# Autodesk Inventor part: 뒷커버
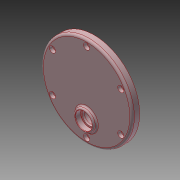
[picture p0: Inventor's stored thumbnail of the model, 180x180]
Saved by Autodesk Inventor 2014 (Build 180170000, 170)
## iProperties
Created: 2024-02
Part Number: 뒷커버
Material: 알루미늄 6061
Document SubType Name: Modeling
Designer: mdu-01
Density: 2.71 g/cm^3
Mass: 304.887 g
Surface Area: 294.624 cm^2
Volume: 112.504 cm^3
Appearance: 기본값(1)
Author: mdu-01
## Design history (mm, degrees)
sketch "스케치1"
  geometry: C1 r 60 at (0, 0) reference; C2 r 44 at (0, 0) reference; C3 r 11 at (0, -31) reference; C4 r 11 at (0, 0) reference; C5 r 46 at (0, 0) reference; A1 r 41 centre (0, 0) between (20.39, -35.57) and (-20.39, -35.57); A2 r 16 centre (0, 0) between (9.254, -13.053) and (-9.254, -13.053); A3 r 16 centre (0, -31) between (15.914, -32.657) and (9.254, -17.947); A4 r 16 centre (0, -31) between (-9.254, -17.947) and (-15.914, -32.657); A5 r 3 centre (18.898, -32.968) between (15.914, -32.657) and (20.39, -35.57); A6 r 3 centre (-18.898, -32.968) between (-20.39, -35.57) and (-15.914, -32.657); A7 r 3 centre (-10.989, -15.5) between (-9.254, -17.947) and (-9.254, -13.053); A8 r 3 centre (10.989, -15.5) between (9.254, -13.053) and (9.254, -17.947); 1 further point
  constraints: 16 point on circle, 8 centre point, 8 tangent, 5 equal radius
  dimensions: "d2" = 5 radial gap between concentric circles of C4 A2; "d3" = 3 radius of A5; "d46" = 5 radial gap between concentric circles of C5 A1
  node "참조1"
  node "참조2"
  node "참조3"
  node "참조4"
  node "참조11"
extrude "돌출1" new body sketch "스케치1" distance "d4" = 10; taper "d5" = 0 deg
extrude "돌출2" join sketch "스케치1" distance "d6" = 3; taper "d7" = 0 deg
chamfer "모따기1" distance "d8" = 1; stored, may be unused: second distance "d9" = 2, angle "d10" = 45 deg
sketch "스케치2"
  geometry: C1 r 13.5 at (0, -31); A1 r 3.5 centre (0, -31) between (1, -34.354) and (-1, -34.354) reference; 1 further point
  constraints: 1 centre point
  dimensions: "d11" = 27 diameter of C1
extrude "돌출3" join sketch "스케치2" distance "d14" = 4; taper "d15" = 0 deg
fillet "모깎기1" dims "d16" = 3
sketch "스케치3"
  geometry: C1 r 1.621 at (0, 52) reference; 1 further point
hole "구멍1" sketch "스케치3" at (0, 52) diameter "d18" = 4.5; stored, may be unused: countersink angle "d22" = 90 deg, drill point angle "d24" = 118 deg; dims "d19" = 6, "d20" = 8, "d21" = 4.4, "d23" = 8
fillet "모깎기2" dims "d31" = 2
sketch "스케치4"
  geometry: L1 (11, 3.7)-(11, -2.7) reference; L2 (-10.7, 4)-(10.7, 4) reference; L3 (10.7, -3)-(-10.7, -3) reference; L4 (10.7, -3)-(11, -3); L5 (11, -3)-(11, -2.7); L6 (6, 7)-(0, 7); L7 (0, 7)-(0, -3); L8 (10.7, 4)-(9, 4); A1 r 0.3 centre (10.7, 3.7) between (11, 3.7) and (10.7, 4); A2 r 3 centre (6, 4) between (9, 4) and (6, 7); 1 further point
  constraints: 13 end point, 4 point on circle, 3 tangent, 2 centre point, 2 collinear, 2 perpendicular, 2 point on line, 1 midpoint, 1 vertical, 2 other
  dimensions: "d33" = 3 distance from line of L6.start L2; "d34" = 2 distance from line of L8.end L1
revolve "회전1" sketch "스케치4" stored, may be unused: angle "d35" = 90 deg
sketch "스케치5"
  geometry: L1 (-20.3, -3)-(-41.7, -3) reference; L2 (-20, 3.7)-(-20, -2.7) reference; L3 (-41.7, 4)-(-20.3, 4) reference; L4 (-42.5, 14)-(-19.5, 14) reference; L5 (-20.3, -3)-(-20, -3); L6 (-20, -3)-(-20, -2.7); L7 (-20.3, 4)-(-22, 4); L8 (-20, 13.3)-(-20, 7); L9 (-20.3, 6.7)-(-22, 6.7); L10 (-22, 6.7)-(-22, 4); L11 (-19.596, 14)-(-20, 13.3); L12 (-31, -3)-(-31, 14); A1 r 0.3 centre (-20.3, 3.7) between (-20, 3.7) and (-20.3, 4); A2 r 0.3 centre (-20.3, 7) between (-20.3, 6.7) and (-20, 7); 1 further point
  constraints: 18 end point, 4 point on circle, 3 perpendicular, 3 tangent, 2 centre point, 2 midpoint, 2 parallel, 2 point on line, 1 vertical, 2 other
  dimensions: "d36" = 7.3 distance between parallel lines of L9 L4; "d37" = 2 distance between parallel lines of L2 L10; "d38" = 0.7 distance from line of L8.start L4; "d39" = 30 deg angle of L8 L11; "d40" = 22 diameter of L8 L12; "d41" = 0.3 radius of A2
revolve "회전2" sketch "스케치5" stored, may be unused: angle "d42" = 90 deg
chamfer "모따기2" distance "d43" = 0.5; stored, may be unused: second distance "d44" = 2, angle "d45" = 45 deg
node "솔리드1"
pattern_circular "원형 패턴1" dims angle "d26" = 360 deg
node "참조5"
node "참조6"
node "참조7"
node "참조8"
node "참조9"
node "참조10"
other parameters: "d1" = 5
